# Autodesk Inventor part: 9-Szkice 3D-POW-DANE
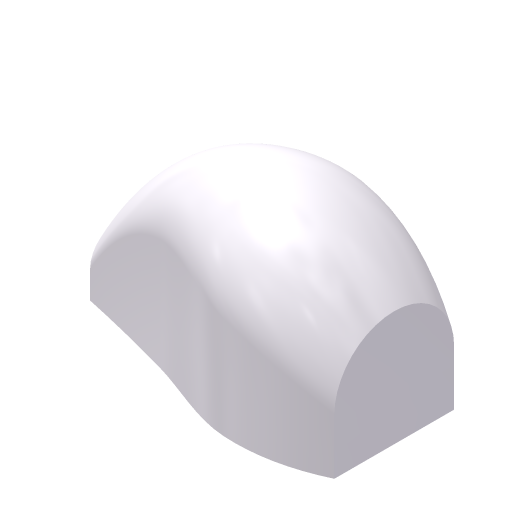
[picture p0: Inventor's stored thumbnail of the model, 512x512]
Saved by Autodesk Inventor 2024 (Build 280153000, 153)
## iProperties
Company: ATC
Created: 2023-03
Part Number: 9-Szkice 3D-POW-DANE
Document SubType Name: Modeling
Designer: Andrzej Jaskulski
Density: 1 g/cm^3
Material: Kurs-AJ
Appearance: Kurs-AJ
Checked By: A.J.
Engr Approved By: Andrzej Jaskulski
Mfg Approved By: Andrzej Jaskulski
Authority: A.J.
Title: A.J.: Kurs R2024-MEP
Author: Andrzej Jaskulski
Revision Number: 1/24
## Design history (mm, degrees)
node "Przekrój 4"
  node "Przekrój 3"
sketch "Szkic XZ"
  geometry: L1 (-6.5, 0)-(6.5, 0); L2 (6.5, 0)-(6.5, 6); L3 (-6.5, 6)-(-6.5, 0); A1 r 6.5 centre (0, 6) between (6.5, 6) and (-6.5, 6); 1 further point
  constraints: 6 end point, 2 point on circle, 2 tangent, 1 centre point, 1 horizontal, 1 midpoint, 1 parallel, 1 perpendicular, 1 other
  dimensions: "d11" = 13 distance of L1.start L1.end; "d12" = 6 distance of L1.end L2.end
sketch "Szkic 2"
  geometry: L1 (-8.5, 0)-(8.5, 0); L2 (8.5, 0)-(8.5, 11); L3 (-8.5, 11)-(-8.5, 0); A1 r 8.5 centre (0, 11) between (8.5, 11) and (-8.5, 11); 1 further point
  constraints: 6 end point, 2 point on circle, 2 tangent, 1 centre point, 1 horizontal, 1 midpoint, 1 parallel, 1 perpendicular, 1 other
  dimensions: "d13" = 17 distance of L1.start L1.end; "d14" = 11 distance of L1.end L2.end
sketch "Szkic 3"
  geometry: L1 (-5.5, 0)-(5.5, 0); L2 (5.5, 0)-(5.5, 12); L3 (-5.5, 12)-(-5.5, 0); A1 r 5.5 centre (0, 12) between (5.5, 12) and (-5.5, 12); 1 further point
  constraints: 6 end point, 2 point on circle, 2 tangent, 1 centre point, 1 horizontal, 1 midpoint, 1 parallel, 1 perpendicular, 1 other
  dimensions: "d15" = 11 distance of L1.start L1.end; "d16" = 12 distance of L1.end L2.end
sketch "Szkic 4"
  geometry: L1 (-3, 0)-(3, 0); L2 (3, 0)-(3, 3); L3 (-3, 3)-(-3, 0); A1 r 3 centre (0, 3) between (3, 3) and (-3, 3); 1 further point
  constraints: 6 end point, 2 point on circle, 2 tangent, 1 centre point, 1 horizontal, 1 midpoint, 1 parallel, 1 perpendicular, 1 other
  dimensions: "d17" = 6 distance of L1.start L1.end; "d18" = 3 distance of L1.end L2.end
feature "BAZA" sketch "Szkic XZ", "Szkic 2", "Szkic 3", "Szkic 4" dims "d3" = 0, "d4" = 90 deg, "d5" = 0, "d6" = 90 deg, "d7" = 0, "d8" = 90 deg, "d9" = 0, "d10" = 90 deg
node "NAD Bryłą"
sketch "ŚCIEŻKA 2D"
  geometry: L1 (-30, -3)-(-30, 3) reference; L2 (-32, 0)-(2, 0); L3 (0, -6.5)-(0, 6.5) reference; L4 (-1.337, -1.946)-(-5.946, -3.715); L5 (-11.846, -4.279)-(-32, -0.692); L6 (-11.846, 4.279)-(-32, 0.692); L7 (-1.337, 1.946)-(-5.946, 3.715); A1 r 2.084 centre (-2.084, 0) between (-1.337, -1.946) and (-1.337, 1.946); A2 r 11.057 centre (-9.909, 6.607) between (-11.846, -4.279) and (-5.946, -3.715); A3 r 11.057 centre (-9.909, -6.607) between (-5.946, 3.715) and (-11.846, 4.279); 1 further point
  constraints: 10 end point, 7 point on circle, 5 symmetric about line, 3 centre point, 3 tangent, 1 horizontal alignment, 1 perpendicular, 1 point on line, 3 other
  dimensions: "d20" = 2 distance from line of L2.start L1; "d21" = 2 distance from line of L3 L2.end
sketch "Profil ROWKA"
  geometry: L1 (-12.5, 0)-(-6, 0) reference; C1 r 0.75 at (-12.5, 0)
  constraints: 1 centre point, 1 coincident
  dimensions: "d39" = 1.5 diameter of C1
node "Bryła1"
node "Korpusy bryłowe"
node "Korpusy powierzchniowe"
node "Przekrój 2"
other parameters: "d19" = 22
